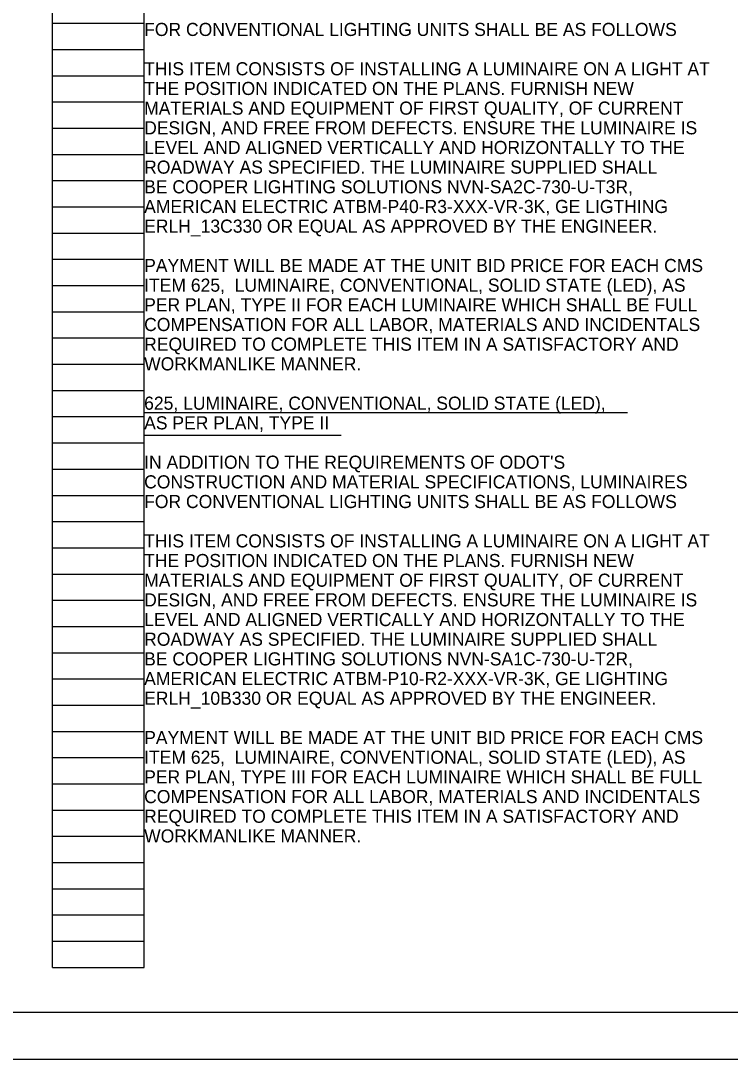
# Model space of a CAD drawing. Extents: x 0 to 59.1, y 0 to 22.
# Drawn here: x 15.92 to 23.5, y 0 to 11.09 of the extents above; entities that cross this region are included whole.
import ezdxf

# ---------------------------------------------------------------- set-up
doc = ezdxf.new("R2010")
doc.units = 0
for name, color, linetype in [('SH_Border', 7, 'Continuous'), ('SH_Cut_Line', 7, 'Continuous'), ('SH_Data', 7, 'Continuous'), ('SH_Text', 7, 'Continuous')]:
    doc.layers.add(name, color=color, linetype=linetype)

msp = doc.modelspace()

# ---------------------------------------------------------------- linework, layer by layer
at = {"layer": 'SH_Border'}
msp.add_lwpolyline([(1.5, 21.5), (33.5, 21.5), (33.5, 0.5), (1.5, 0.5)], close=True, dxfattribs=at)
at = {"layer": 'SH_Cut_Line'}
msp.add_lwpolyline([(0, 0), (34, 0), (34, 22), (0, 22)], close=True, dxfattribs=at)
at = {"layer": 'SH_Data'}
for p, q in [((16.26, 0.98), (16.26, 21.14)), ((17.24, 0.98), (17.24, 21.14)), ((16.26, 11.06), (17.24, 11.06)), ((16.26, 10.78), (17.24, 10.78)), ((16.26, 10.5), (17.24, 10.5)), ((16.26, 10.22), (17.24, 10.22)), ((16.26, 9.94), (17.24, 9.94)), ((16.26, 9.66), (17.24, 9.66)), ((16.26, 9.38), (17.24, 9.38)), ((16.26, 9.1), (17.24, 9.1)), ((16.26, 8.82), (17.24, 8.82)), ((16.26, 8.54), (17.24, 8.54)), ((16.26, 8.26), (17.24, 8.26)), ((16.26, 7.98), (17.24, 7.98)), ((16.26, 7.7), (17.24, 7.7)), ((16.26, 7.42), (17.24, 7.42)), ((16.26, 7.14), (17.24, 7.14)), ((16.26, 6.86), (17.24, 6.86)), ((16.26, 6.58), (17.24, 6.58)), ((16.26, 6.3), (17.24, 6.3)), ((16.26, 6.02), (17.24, 6.02)), ((16.26, 5.74), (17.24, 5.74)), ((16.26, 5.46), (17.24, 5.46)), ((16.26, 5.18), (17.24, 5.18)), ((16.26, 4.9), (17.24, 4.9)), ((16.26, 4.62), (17.24, 4.62)), ((16.26, 4.34), (17.24, 4.34)), ((16.26, 4.06), (17.24, 4.06)), ((16.26, 3.78), (17.24, 3.78)), ((16.26, 3.5), (17.24, 3.5)), ((16.26, 3.22), (17.24, 3.22)), ((16.26, 2.94), (17.24, 2.94)), ((16.26, 2.66), (17.24, 2.66)), ((16.26, 2.38), (17.24, 2.38)), ((16.26, 2.1), (17.24, 2.1)), ((16.26, 1.82), (17.24, 1.82)), ((16.26, 1.54), (17.24, 1.54)), ((16.26, 1.26), (17.24, 1.26)), ((16.26, 0.98), (17.24, 0.98))]:
    msp.add_line(p, q, dxfattribs=at)
at = {"layer": 'SH_Text'}
for p, q in [((17.238, 6.904), (22.4, 6.904)), ((17.238, 6.661), (19.343, 6.661))]:
    msp.add_line(p, q, dxfattribs=at)

# ---------------------------------------------------------------- texts
for s, p in [('FOR CONVENTIONAL LIGHTING UNITS SHALL BE AS FOLLOWS', (17.238, 10.924)), ('THIS ITEM CONSISTS OF INSTALLING A LUMINAIRE ON A LIGHT AT ', (17.238, 10.504)), ('THE POSITION INDICATED ON THE PLANS. FURNISH NEW ', (17.238, 10.294)), ('MATERIALS AND EQUIPMENT OF FIRST QUALITY, OF CURRENT ', (17.238, 10.084)), ('DESIGN, AND FREE FROM DEFECTS. ENSURE THE LUMINAIRE IS ', (17.238, 9.874)), ('LEVEL AND ALIGNED VERTICALLY AND HORIZONTALLY TO THE ', (17.238, 9.664)), ('ROADWAY AS SPECIFIED. THE LUMINAIRE SUPPLIED SHALL ', (17.238, 9.454)), ('BE COOPER LIGHTING SOLUTIONS NVN-SA2C-730-U-T3R, ', (17.238, 9.244)), ('AMERICAN ELECTRIC ATBM-P40-R3-XXX-VR-3K, GE LIGTHING ', (17.238, 9.034)), ('ERLH_13C330 OR EQUAL AS APPROVED BY THE ENGINEER. ', (17.238, 8.824)), ('PAYMENT WILL BE MADE AT THE UNIT BID PRICE FOR EACH CMS ', (17.238, 8.404)), ('ITEM 625,  LUMINAIRE, CONVENTIONAL, SOLID STATE (LED), AS ', (17.238, 8.194)), ('PER PLAN, TYPE II FOR EACH LUMINAIRE WHICH SHALL BE FULL ', (17.238, 7.984)), ('COMPENSATION FOR ALL LABOR, MATERIALS AND INCIDENTALS ', (17.238, 7.774)), ('REQUIRED TO COMPLETE THIS ITEM IN A SATISFACTORY AND ', (17.238, 7.564)), ('WORKMANLIKE MANNER.', (17.238, 7.354)), ('625, LUMINAIRE, CONVENTIONAL, SOLID STATE (LED), ', (17.238, 6.934)), ('AS PER PLAN, TYPE II', (17.238, 6.724)), ("IN ADDITION TO THE REQUIREMENTS OF ODOT'S ", (17.238, 6.304)), ('CONSTRUCTION AND MATERIAL SPECIFICATIONS, LUMINAIRES ', (17.238, 6.094)), ('FOR CONVENTIONAL LIGHTING UNITS SHALL BE AS FOLLOWS', (17.238, 5.884)), ('THIS ITEM CONSISTS OF INSTALLING A LUMINAIRE ON A LIGHT AT ', (17.238, 5.464)), ('THE POSITION INDICATED ON THE PLANS. FURNISH NEW ', (17.238, 5.254)), ('MATERIALS AND EQUIPMENT OF FIRST QUALITY, OF CURRENT ', (17.238, 5.044)), ('DESIGN, AND FREE FROM DEFECTS. ENSURE THE LUMINAIRE IS ', (17.238, 4.834)), ('LEVEL AND ALIGNED VERTICALLY AND HORIZONTALLY TO THE ', (17.238, 4.624)), ('ROADWAY AS SPECIFIED. THE LUMINAIRE SUPPLIED SHALL ', (17.238, 4.414)), ('BE COOPER LIGHTING SOLUTIONS NVN-SA1C-730-U-T2R,  ', (17.238, 4.204)), ('AMERICAN ELECTRIC ATBM-P10-R2-XXX-VR-3K, GE LIGHTING ', (17.238, 3.994)), ('ERLH_10B330 OR EQUAL AS APPROVED BY THE ENGINEER. ', (17.238, 3.784)), ('PAYMENT WILL BE MADE AT THE UNIT BID PRICE FOR EACH CMS ', (17.238, 3.364)), ('ITEM 625,  LUMINAIRE, CONVENTIONAL, SOLID STATE (LED), AS ', (17.238, 3.154)), ('PER PLAN, TYPE III FOR EACH LUMINAIRE WHICH SHALL BE FULL ', (17.238, 2.944)), ('COMPENSATION FOR ALL LABOR, MATERIALS AND INCIDENTALS ', (17.238, 2.734)), ('REQUIRED TO COMPLETE THIS ITEM IN A SATISFACTORY AND ', (17.238, 2.524)), ('WORKMANLIKE MANNER.', (17.238, 2.314))]:
    msp.add_text(s, height=0.14, dxfattribs=at).set_placement(p)

doc.saveas('drawing.dxf')
